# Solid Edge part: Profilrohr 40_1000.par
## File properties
Username: ahadarics
Dokumentum tartalom típus: 0
Author: ahadarics
Last saved by: ahadarics
Revision: 101
Sűrűség: 0,000 kg/m^3
Pontosság: 0,990
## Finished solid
Body 1: solid body, 175 faces, 519 edges, 346 vertices.
  Faces by surface: cylinder 107, plane 68
  Edges by curve: line 305, circle 214
Bounding box of the edges (mm): 51.354 x 51.354 x 1043.000, from (-25.6768, -25.6768, -934) to (25.6768, 25.6768, 109).
Cylindrical faces by radius (mm): R0.1 x16, R0.2 x30, R0.5 x28, R1 x8, R2.7 x8, R3.5 x4, R5 x4, R20 x1, R22 x8
Planar faces by outward normal: +x 6, +y 6, +z 1, -x 4, -y 4, -z 1, oblique 46
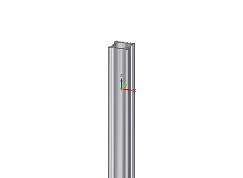
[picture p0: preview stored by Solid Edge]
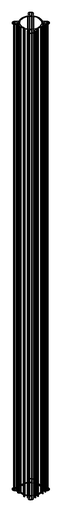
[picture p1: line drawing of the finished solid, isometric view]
